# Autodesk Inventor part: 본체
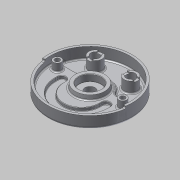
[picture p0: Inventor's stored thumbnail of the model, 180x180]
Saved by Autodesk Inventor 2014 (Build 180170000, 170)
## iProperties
Created: 2015-06
Part Number: 본체
Material: 알루미늄 6061
Document SubType Name: Modeling
Designer: MYHOME
Density: 2.71 g/cm^3
Appearance: 알루미늄 - 평지
Mass: 1070.98 g
Surface Area: 1034.41 cm^2
Volume: 395.194 cm^3
Author: MYHOME
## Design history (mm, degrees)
sketch "스케치1"
  geometry: C1 r 95 at (0, 0); 1 further point
  constraints: 1 centre point, 1 coincident
  dimensions: "d0" = 190 diameter of C1
extrude "돌출1" new body sketch "스케치1" distance "d1" = 32; taper "d2" = 0 deg
sketch "스케치2"
  geometry: C1 r 95 at (0, 0) reference; C2 r 90 at (0, 0)
  constraints: 1 centre point, 1 coincident
  dimensions: "d3" = 180 diameter of C2
extrude "돌출2" cut sketch "스케치2" distance "d4" = 25; taper "d5" = 0 deg
sketch "스케치3"
  geometry: L1 (-38.833, 16)-(-88.566, 16); L2 (38.833, 16)-(88.566, 16); C1 r 90 at (0, 0) reference; A1 r 42 centre (0, 0) between (38.833, 16) and (-38.833, 16); A2 r 90 centre (0, 0) between (-88.566, 16) and (88.566, 16)
  constraints: 4 end point, 4 point on circle, 2 centre point, 2 coincident, 1 collinear, 1 horizontal
  dimensions: "d6" = 84 diameter of A1; "d7" = 16 distance from line of A1.centre L1; "d8" = 16 distance from line of C1.centre L2; "d9" = 180 diameter of A2
extrude "돌출3" join sketch "스케치3" distance "d10" = 7; taper "d11" = 0 deg
fillet "모깎기1" dims "d12" = 10
sketch "스케치4"
  geometry: L1 (-95, 0)-(95, 0); L2 (0, 0)-(-94.075, -13.221); L3 (0, 0)-(94.075, -13.221); C1 r 90 at (0, 0) reference; C2 r 95 at (0, 0); A1 r 95 centre (0, 0) between (-95, 0) and (95, 0) reference; A2 r 90 centre (0, 0) between (-89.124, -12.526) and (89.124, -12.526); 2 further points
  constraints: 6 end point, 6 point on circle, 4 coincident, 2 centre point, 2 point on line, 1 horizontal, 1 midpoint
  dimensions: "d13" = 8 deg angle of L2 L1; "d14" = 8 deg angle of L3 L1; "d15" = 180 diameter of A2; "d16" = 190 diameter of C2
extrude "돌출4" cut sketch "스케치4" distance "d17" = 5; taper "d18" = 0 deg
sketch "스케치5"
  geometry: C1 r 35 at (0, 0); A1 r 90 centre (0, 0) between (-85.114, 29.25) and (85.114, 29.25) reference
  constraints: 1 centre point, 1 coincident
  dimensions: "d19" = 70 diameter of C1
extrude "돌출5" join sketch "스케치5" distance "d20" = 10; taper "d21" = -10 deg
sketch "스케치6"
  geometry: C1 r 95 at (0, 0) reference; C2 r 26 at (0, 0)
  constraints: 1 centre point, 1 coincident
  dimensions: "d22" = 52 diameter of C2
extrude "돌출6" join sketch "스케치6" distance "d23" = 12; taper "d24" = -15 deg
hole "구멍1" diameter "d27" = 23; stored, may be unused: countersink angle "d31" = 90 deg, drill point angle "d33" = 118 deg; dims "d25" = 10, "d26" = 10, "d28" = 6, "d29" = 50, "d30" = 15, "d32" = 8
sketch "스케치7"
  geometry: C1 r 15 at (-40, 52); C2 r 15 at (40, 52); C3 r 10 at (-40, 52); C4 r 10 at (40, 52); A1 r 90 centre (0, 0) between (85.114, 29.25) and (-85.114, 29.25) reference
  constraints: 4 centre point, 2 coincident, 1 horizontal alignment
  dimensions: "d34" = 30 diameter of C1; "d35" = 30 diameter of C2; "d36" = 52 vertical distance of C1.centre A1.centre; "d37" = 80 distance of C2.centre C1.centre; "d38" = 40 horizontal distance of A1.centre C1.centre; "d39" = 20 diameter of C3; "d40" = 20 diameter of C4
extrude "돌출7" join sketch "스케치7" stored distance "d41" = 12; taper "d42" = 0 deg
extrude "돌출8" cut sketch "스케치7" stored distance "d43" = 12; taper "d44" = 0 deg
sketch "스케치8"
  geometry: L1 (-6, 13.748)-(-6, -13.748); L2 (6, 13.748)-(6, -13.748); L3 (66.252, 6)-(93.748, 6); L4 (66.252, -6)-(93.748, -6); C1 r 10 at (0, 0) reference; C2 r 10 at (80, 0) reference; A1 r 15 centre (0, 0) between (6, 13.748) and (-6, 13.748) reference; A2 r 15 centre (80, 0) between (93.748, 6) and (93.748, -6) reference; A3 r 15 centre (0, 0) between (6, 13.748) and (-6, 13.748); A4 r 15 centre (0, 0) between (-6, -13.748) and (6, -13.748); A5 r 15 centre (80, 0) between (66.252, 6) and (66.252, -6); A6 r 15 centre (80, 0) between (93.748, -6) and (93.748, 6); 1 further point
  constraints: 16 point on circle, 8 end point, 4 centre point, 2 coincident, 2 parallel, 1 perpendicular, 1 vertical
  dimensions: "d45" = 6 distance from line of L2 C1.centre; "d46" = 12 distance between parallel lines of L2 L1; "d47" = 6 distance from line of L3 C2.centre; "d48" = 12 distance between parallel lines of L4 L3
extrude "돌출9" cut sketch "스케치8" distance "d49" = 3; taper "d50" = 0 deg
sketch "스케치9"
  geometry: C1 r 35 at (0, 0) reference; C2 r 9 at (-74, 0); C3 r 9 at (74, 0)
  constraints: 2 centre point, 2 horizontal alignment
  dimensions: "d51" = 18 diameter of C2; "d52" = 18 diameter of C3; "d53" = 148 distance of C3.centre C2.centre; "d54" = 74 distance of C3.centre C1.centre
extrude "돌출10" join sketch "스케치9" stored distance "d55" = 3; taper "d56" = 0 deg
sketch "스케치10"
  geometry: C1 r 9 at (74, 0) reference; C2 r 9 at (-74, 0) reference; 2 further points
  constraints: 2 coincident
hole "구멍2" sketch "스케치10" at (-74, 0), (74, 0) diameter "d57" = 11; stored, may be unused: countersink angle "d61" = 90 deg, drill point angle "d63" = 118 deg; dims "d58" = 6, "d59" = 18, "d60" = 11, "d62" = 8
sketch "스케치11"
  geometry: L1 (75.657, 16)-(45.033, 16) reference; L2 (59, -19)-(59, -14); L3 (41, -19)-(41, -14); L4 (-41, -19)-(-41, -14); L5 (-59, -19)-(-59, -14); L6 (59, -14)-(41, -14); L7 (-41, -14)-(-59, -14); C1 r 35 at (0, 0) reference; A1 r 42 centre (0, 0) between (36.373, 21) and (-36.373, 21) reference; A2 r 41 centre (0, -19) between (-41, -19) and (41, -19); A3 r 59 centre (0, -19) between (-59, -19) and (59, -19); A4 r 9 centre (50, -14) between (59, -14) and (41, -14); A5 r 9 centre (-50, -14) between (-41, -14) and (-59, -14)
  constraints: 12 end point, 8 point on circle, 4 centre point, 4 equal length, 4 horizontal alignment, 4 tangent, 2 midpoint, 2 perpendicular, 1 coincident, 1 collinear, 1 vertical alignment
  dimensions: "d66" = 19 distance of A2.centre C1.centre; "d67" = 41 radius of A2; "d68" = 59 radius of A3; "d69" = 5 distance of L2.start L2.end
extrude "돌출11" cut sketch "스케치11" distance "d70" = 7; taper "d71" = 0 deg
sketch "스케치12"
  geometry: C1 r 95 at (0, 0) reference; C2 r 68 at (0, 0)
  constraints: 1 centre point, 1 coincident, 1 other
  dimensions: "d72" = 136 diameter of C2
feature "엠보싱1" sketch "스케치12" dims "d1" = 32, "d73" = 0.5, "d74" = 0
fillet "모깎기3" dims "d76" = 3
fillet "모깎기4" dims "d77" = 3
fillet "모깎기5" dims "d78" = 3
fillet "모깎기6" dims "d79" = 1
fillet "모깎기7" dims "d80" = 0.3
chamfer "모따기1" distance "d81" = 1; stored, may be unused: second distance "d82" = 2, angle "d83" = 45 deg
fillet "모깎기8" dims "d84" = 3
fillet "모깎기9" dims "d85" = 3
fillet "모깎기10" dims "d86" = 3
fillet "모깎기11" dims "d87" = 5
node "솔리드1"
node "투영된 루프1"
node "투영된 루프2"
